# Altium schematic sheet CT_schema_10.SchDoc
size 254 x 194 mm
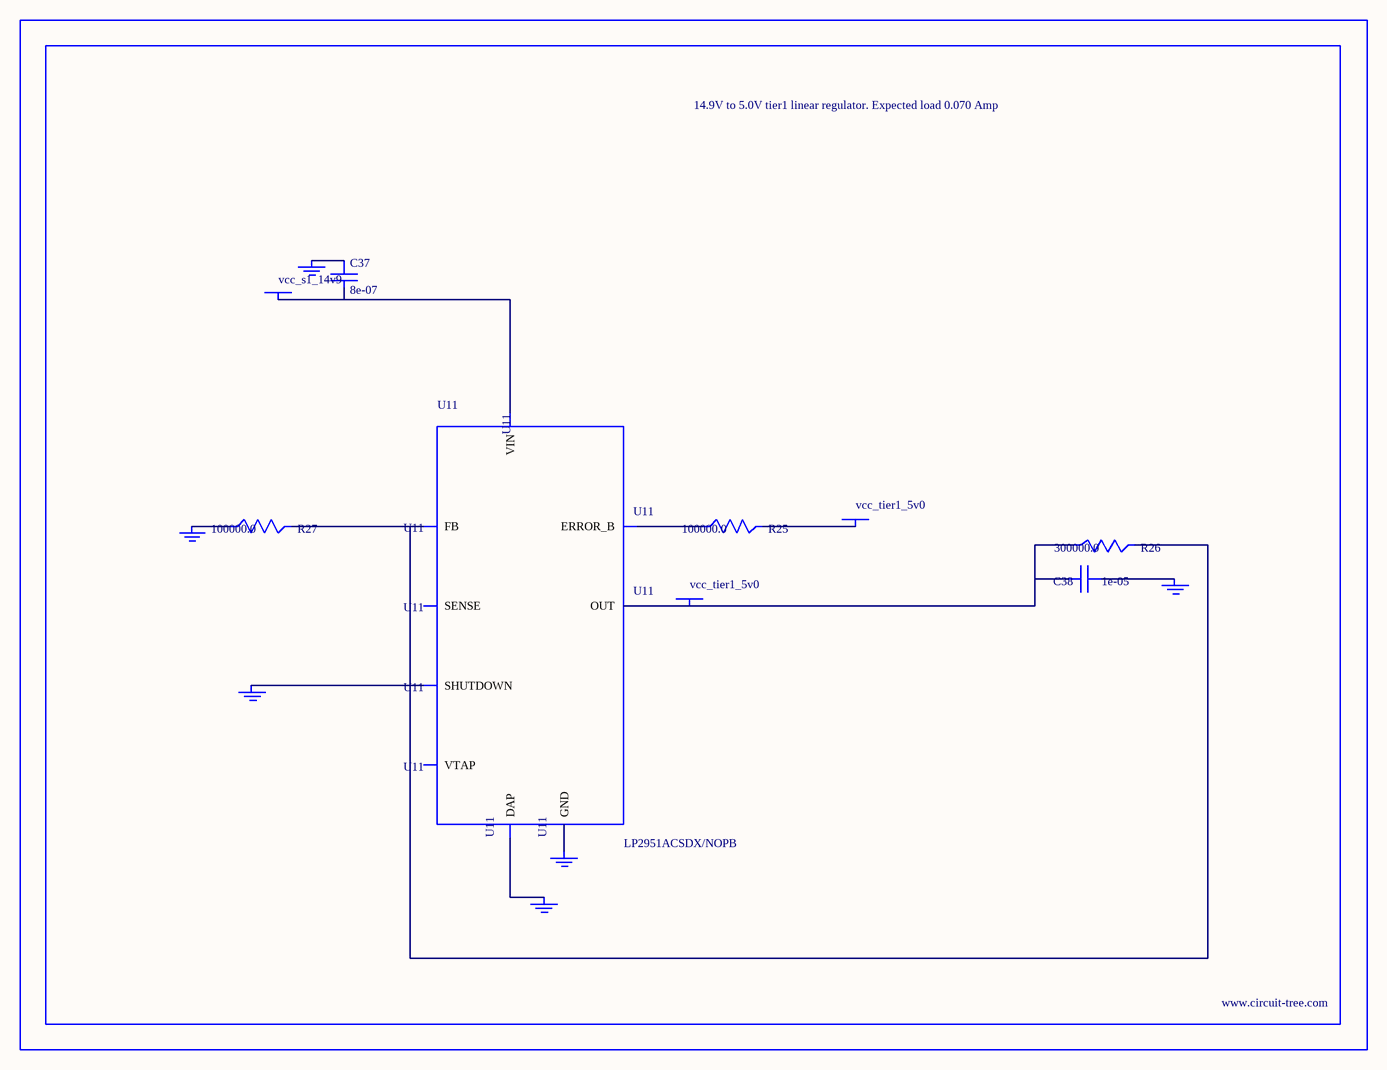
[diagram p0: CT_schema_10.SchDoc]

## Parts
BORDER9  (no value)
C37  8e-07  [R0603]
C38  1e-05  [C1210]
GND_INSTANCE_9_0  (no value)
GND_INSTANCE_9_1  (no value)
GND_INSTANCE_9_2  (no value)
GND_INSTANCE_9_3  (no value)
GND_INSTANCE_9_4  (no value)
GND_INSTANCE_9_5  (no value)
POWER_INSTANCE_9_0  vcc_tier1_5v0
POWER_INSTANCE_9_1  vcc_s1_14v9
POWER_INSTANCE_9_2  vcc_tier1_5v0
R25  100000.0  [R0603]
R26  300000.0  [R0603]
R27  100000.0  [R0603]
U11  LP2951ACSDX/NOPB  [WSON-8]

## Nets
NetC37_1: C37.1 GND_INSTANCE_9_3.0(GND)
NetC37_2: C37.2 POWER_INSTANCE_9_1.0(PWR) U11.8(VIN)
NetC38_1: C38.1 GND_INSTANCE_9_0.0(GND)
NetC38_2: C38.2 POWER_INSTANCE_9_2.0(PWR) R26.1 U11.1(OUT)
NetGND_INSTANCE_9_1_0: GND_INSTANCE_9_1.0(GND) U11.3(SHUTDOWN)
NetGND_INSTANCE_9_2_0: GND_INSTANCE_9_2.0(GND) R27.1
NetGND_INSTANCE_9_4_0: GND_INSTANCE_9_4.0(GND) U11.PAD(DAP)
NetGND_INSTANCE_9_5_0: GND_INSTANCE_9_5.0(GND) U11.4(GND)
NetPOWER_INSTANCE_9_0_0: POWER_INSTANCE_9_0.0(PWR) R25.2
NetR25_1: R25.1 U11.5(ERROR_B)
NetR26_2: R26.2 R27.2 U11.7(FB)

Not connected (* = marked no-connect by the designer): U11 2(SENSE) 6(VTAP)

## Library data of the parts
BORDER9 = BORDER_PAGE9
C37 = C37
C38 = GRM32DR61E106MA12L
GND_INSTANCE_9_0-GND_INSTANCE_9_5 = GND
POWER_INSTANCE_9_0-POWER_INSTANCE_9_2 = PWR
R25 R27 = RC0603JR-07100KL
R26 = RC0603JR-07300KL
